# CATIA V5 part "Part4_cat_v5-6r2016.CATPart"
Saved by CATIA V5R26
Part number: Guide
Bounding box of the stored display mesh (mm): x -5 to 5, y -5 to 5, z -25 to 25
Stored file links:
  D:\_Deepak\CATIA\CATIA V5 2015 Parts Files\Tutorial Files\Tutorials\c16_catia_v5_6r2016_tut\Cam Follower mechanism\Part4_cat_v5-6r2016.CATPart
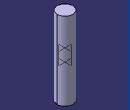
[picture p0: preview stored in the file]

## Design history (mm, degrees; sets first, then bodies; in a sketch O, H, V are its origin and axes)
Body1 (main body)
  Sketch1 on xy-plane, origin (0, 0, 0), H (1, 0, 0), V (0, 1, 0)
    circle A1 centre (0, 0) radius 5
    radius A1 = 5
  Pad1: profile Sketch1, direction (0, 0, 1), length 25, mirrored extent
